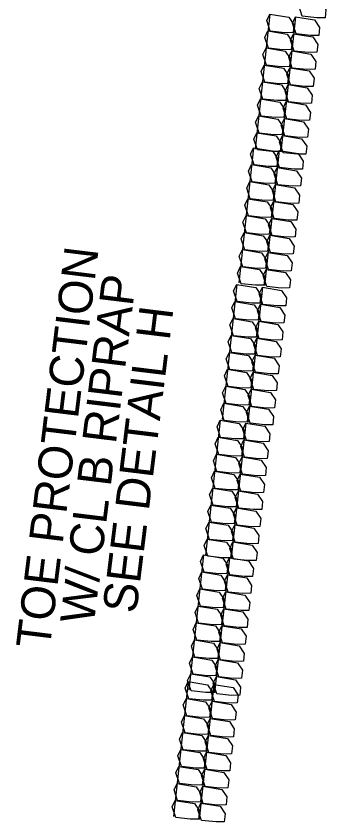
# Model space of a CAD drawing. Extents: x 465700 to 483515, y 488970 to 507540.
# Drawn here: x 481164.1 to 481209.7, y 490401.6 to 490519.9 of the extents above; entities that cross this region are included whole.
import ezdxf

# ---------------------------------------------------------------- set-up
doc = ezdxf.new("R2010")
doc.units = 0
doc.layers.add('Prop Erosion Embankment Toe Protection CELL', color=7, linetype='Continuous')
doc.layers.add('Prop Erosion Embankment Toe Protection Label', color=7, linetype='Continuous')

msp = doc.modelspace()

# ---------------------------------------------------------------- linework, layer by layer
at = {"layer": 'Prop Erosion Embankment Toe Protection CELL'}
for p, q in [((481201.41, 490520.24), (481199.25, 490500.36)), ((481205.19, 490519.83), (481203.03, 490499.95)), ((481199.01, 490500.55), (481196.84, 490480.67)), ((481202.79, 490500.14), (481200.62, 490480.26)), ((481196.55, 490480.41), (481194.38, 490460.53)), ((481200.33, 490480), (481198.16, 490460.12)), ((481194.11, 490460.42), (481191.94, 490440.54)), ((481197.88, 490460.01), (481195.72, 490440.13)), ((481191.68, 490440.59), (481189.52, 490420.7)), ((481195.46, 490440.18), (481193.3, 490420.29)), ((481189.41, 490421.95), (481187.24, 490402.07)), ((481193.19, 490421.54), (481191.02, 490401.66))]:
    msp.add_line(p, q, dxfattribs=at)
for points in [[(481209.54, 490519.69), (481208.33, 490519.67), (481206.19, 490519.91), (481205.66, 490521.47), (481206.11, 490522.43), (481208.93, 490521.97), (481209.67, 490520.88), (481209.54, 490519.69)], [(481204.84, 490517.5), (481203.63, 490517.48), (481201.49, 490517.72), (481200.96, 490519.28), (481201.41, 490520.24), (481204.23, 490519.78), (481204.96, 490518.67), (481204.84, 490517.5)], [(481208.61, 490517.09), (481207.41, 490517.07), (481205.27, 490517.3), (481204.73, 490518.87), (481205.19, 490519.83), (481208.01, 490519.37), (481208.74, 490518.26), (481208.61, 490517.09)], [(481204.57, 490515.02), (481203.35, 490514.97), (481201.22, 490515.21), (481200.69, 490516.8), (481201.14, 490517.75), (481203.96, 490517.27), (481204.69, 490516.16), (481204.57, 490515.02)], [(481208.34, 490514.61), (481207.13, 490514.56), (481204.99, 490514.79), (481204.46, 490516.39), (481204.92, 490517.34), (481207.73, 490516.86), (481208.47, 490515.75), (481208.34, 490514.61)], [(481204.29, 490512.51), (481203.08, 490512.46), (481200.94, 490512.7), (481200.41, 490514.29), (481200.87, 490515.24), (481203.68, 490514.76), (481204.42, 490513.67), (481204.29, 490512.51)], [(481208.07, 490512.1), (481206.86, 490512.05), (481204.72, 490512.28), (481204.19, 490513.88), (481204.65, 490514.83), (481207.46, 490514.35), (481208.2, 490513.26), (481208.07, 490512.1)], [(481204.02, 490510), (481202.81, 490509.98), (481200.67, 490510.21), (481200.14, 490511.78), (481200.6, 490512.73), (481203.41, 490512.28), (481204.15, 490511.19), (481204.02, 490510)], [(481207.8, 490509.59), (481206.59, 490509.57), (481204.45, 490509.8), (481203.92, 490511.37), (481204.37, 490512.32), (481207.19, 490511.86), (481207.93, 490510.78), (481207.8, 490509.59)], [(481203.75, 490507.51), (481202.54, 490507.49), (481200.4, 490507.72), (481199.87, 490509.29), (481200.33, 490510.25), (481203.14, 490509.79), (481203.88, 490508.68), (481203.75, 490507.51)], [(481207.53, 490507.1), (481206.32, 490507.08), (481204.18, 490507.31), (481203.65, 490508.88), (481204.1, 490509.84), (481206.92, 490509.38), (481207.65, 490508.27), (481207.53, 490507.1)], [(481203.48, 490505.03), (481202.27, 490504.98), (481200.13, 490505.21), (481199.6, 490506.81), (481200.05, 490507.76), (481202.87, 490507.28), (481203.6, 490506.17), (481203.48, 490505.03)], [(481207.26, 490504.61), (481206.04, 490504.57), (481203.91, 490504.8), (481203.38, 490506.4), (481203.83, 490507.35), (481206.65, 490506.87), (481207.38, 490505.76), (481207.26, 490504.61)], [(481203.21, 490502.52), (481201.99, 490502.47), (481199.86, 490502.7), (481199.33, 490504.3), (481199.78, 490505.25), (481202.6, 490504.77), (481203.33, 490503.68), (481203.21, 490502.52)], [(481206.98, 490502.1), (481205.77, 490502.06), (481203.63, 490502.29), (481203.1, 490503.88), (481203.56, 490504.84), (481206.37, 490504.36), (481207.11, 490503.27), (481206.98, 490502.1)], [(481202.93, 490500.01), (481201.72, 490499.99), (481199.59, 490500.22), (481199.05, 490501.79), (481199.51, 490502.74), (481202.33, 490502.28), (481203.06, 490501.2), (481202.93, 490500.01)], [(481206.71, 490499.59), (481205.5, 490499.58), (481203.36, 490499.81), (481202.83, 490501.37), (481203.29, 490502.33), (481206.1, 490501.87), (481206.84, 490500.79), (481206.71, 490499.59)], [(481202.43, 490497.81), (481201.22, 490497.8), (481199.09, 490498.03), (481198.55, 490499.59), (481199.01, 490500.55), (481201.83, 490500.09), (481202.56, 490498.98), (481202.43, 490497.81)], [(481206.21, 490497.4), (481205, 490497.38), (481202.86, 490497.62), (481202.33, 490499.18), (481202.79, 490500.14), (481205.6, 490499.68), (481206.34, 490498.57), (481206.21, 490497.4)], [(481202.16, 490495.33), (481200.95, 490495.29), (481198.81, 490495.52), (481198.28, 490497.11), (481198.74, 490498.07), (481201.55, 490497.58), (481202.29, 490496.47), (481202.16, 490495.33)], [(481205.94, 490494.92), (481204.73, 490494.87), (481202.59, 490495.11), (481202.06, 490496.7), (481202.52, 490497.65), (481205.33, 490497.17), (481206.06, 490496.06), (481205.94, 490494.92)], [(481201.89, 490492.82), (481200.68, 490492.77), (481198.54, 490493.01), (481198.01, 490494.6), (481198.46, 490495.56), (481201.28, 490495.07), (481202.02, 490493.99), (481201.89, 490492.82)], [(481205.67, 490492.41), (481204.45, 490492.36), (481202.32, 490492.6), (481201.79, 490494.19), (481202.24, 490495.14), (481205.06, 490494.66), (481205.79, 490493.58), (481205.67, 490492.41)], [(481201.62, 490490.31), (481200.41, 490490.29), (481198.27, 490490.52), (481197.74, 490492.09), (481198.19, 490493.05), (481201.01, 490492.59), (481201.75, 490491.5), (481201.62, 490490.31)], [(481205.39, 490489.9), (481204.18, 490489.88), (481202.05, 490490.11), (481201.51, 490491.68), (481201.97, 490492.63), (481204.79, 490492.18), (481205.52, 490491.09), (481205.39, 490489.9)], [(481201.34, 490487.82), (481200.14, 490487.8), (481198, 490488.04), (481197.46, 490489.6), (481197.92, 490490.56), (481200.74, 490490.1), (481201.47, 490488.99), (481201.34, 490487.82)], [(481205.12, 490487.41), (481203.91, 490487.39), (481201.78, 490487.63), (481201.24, 490489.19), (481201.7, 490490.15), (481204.52, 490489.69), (481205.25, 490488.58), (481205.12, 490487.41)], [(481201.07, 490485.34), (481199.86, 490485.29), (481197.72, 490485.53), (481197.19, 490487.12), (481197.65, 490488.07), (481200.46, 490487.59), (481201.2, 490486.48), (481201.07, 490485.34)], [(481204.85, 490484.93), (481203.64, 490484.88), (481201.5, 490485.12), (481200.97, 490486.71), (481201.43, 490487.66), (481204.24, 490487.18), (481204.98, 490486.07), (481204.85, 490484.93)], [(481200.8, 490482.83), (481199.59, 490482.78), (481197.45, 490483.02), (481196.92, 490484.61), (481197.38, 490485.56), (481200.19, 490485.08), (481200.93, 490484), (481200.8, 490482.83)], [(481204.58, 490482.42), (481203.37, 490482.37), (481201.23, 490482.61), (481200.7, 490484.2), (481201.15, 490485.15), (481203.97, 490484.67), (481204.71, 490483.59), (481204.58, 490482.42)], [(481200.53, 490480.32), (481199.32, 490480.3), (481197.18, 490480.53), (481196.65, 490482.1), (481197.1, 490483.05), (481199.92, 490482.6), (481200.66, 490481.51), (481200.53, 490480.32)], [(481204.31, 490479.91), (481203.1, 490479.89), (481200.96, 490480.12), (481200.43, 490481.69), (481200.88, 490482.64), (481203.7, 490482.19), (481204.44, 490481.1), (481204.31, 490479.91)], [(481199.97, 490477.68), (481198.76, 490477.66), (481196.63, 490477.89), (481196.09, 490479.46), (481196.55, 490480.41), (481199.37, 490479.96), (481200.1, 490478.84), (481199.97, 490477.68)], [(481203.75, 490477.26), (481202.54, 490477.25), (481200.4, 490477.48), (481199.87, 490479.05), (481200.33, 490480), (481203.14, 490479.54), (481203.88, 490478.43), (481203.75, 490477.26)], [(481199.7, 490475.19), (481198.49, 490475.15), (481196.35, 490475.38), (481195.82, 490476.97), (481196.28, 490477.93), (481199.09, 490477.44), (481199.83, 490476.33), (481199.7, 490475.19)], [(481203.48, 490474.78), (481202.27, 490474.74), (481200.13, 490474.97), (481199.6, 490476.56), (481200.06, 490477.52), (481202.87, 490477.03), (481203.6, 490475.92), (481203.48, 490474.78)], [(481199.43, 490472.68), (481198.22, 490472.64), (481196.08, 490472.87), (481195.55, 490474.46), (481196, 490475.42), (481198.82, 490474.93), (481199.56, 490473.85), (481199.43, 490472.68)], [(481203.21, 490472.27), (481201.99, 490472.23), (481199.86, 490472.46), (481199.33, 490474.05), (481199.78, 490475.01), (481202.6, 490474.52), (481203.33, 490473.44), (481203.21, 490472.27)], [(481199.16, 490470.17), (481197.95, 490470.15), (481195.81, 490470.38), (481195.28, 490471.95), (481195.73, 490472.91), (481198.55, 490472.45), (481199.29, 490471.36), (481199.16, 490470.17)], [(481202.93, 490469.76), (481201.72, 490469.74), (481199.59, 490469.97), (481199.05, 490471.54), (481199.51, 490472.5), (481202.33, 490472.04), (481203.06, 490470.95), (481202.93, 490469.76)], [(481198.88, 490467.69), (481197.68, 490467.67), (481195.54, 490467.9), (481195, 490469.47), (481195.46, 490470.42), (481198.28, 490469.96), (481199.01, 490468.85), (481198.88, 490467.69)], [(481202.66, 490467.27), (481201.45, 490467.25), (481199.32, 490467.49), (481198.78, 490469.05), (481199.24, 490470.01), (481202.06, 490469.55), (481202.79, 490468.44), (481202.66, 490467.27)], [(481198.61, 490465.2), (481197.4, 490465.16), (481195.27, 490465.39), (481194.73, 490466.98), (481195.19, 490467.94), (481198, 490467.45), (481198.74, 490466.34), (481198.61, 490465.2)], [(481202.39, 490464.79), (481201.18, 490464.74), (481199.04, 490464.98), (481198.51, 490466.57), (481198.97, 490467.53), (481201.78, 490467.04), (481202.52, 490465.93), (481202.39, 490464.79)], [(481198.34, 490462.69), (481197.13, 490462.65), (481194.99, 490462.88), (481194.46, 490464.47), (481194.92, 490465.43), (481197.73, 490464.94), (481198.47, 490463.86), (481198.34, 490462.69)], [(481202.12, 490462.28), (481200.91, 490462.23), (481198.77, 490462.47), (481198.24, 490464.06), (481198.69, 490465.01), (481201.51, 490464.53), (481202.25, 490463.45), (481202.12, 490462.28)], [(481198.07, 490460.18), (481196.86, 490460.16), (481194.72, 490460.39), (481194.19, 490461.96), (481194.64, 490462.92), (481197.46, 490462.46), (481198.2, 490461.37), (481198.07, 490460.18)], [(481201.85, 490459.77), (481200.64, 490459.75), (481198.5, 490459.98), (481197.97, 490461.55), (481198.42, 490462.5), (481201.24, 490462.05), (481201.98, 490460.96), (481201.85, 490459.77)], [(481197.53, 490457.69), (481196.32, 490457.67), (481194.18, 490457.9), (481193.65, 490459.47), (481194.11, 490460.42), (481196.92, 490459.97), (481197.66, 490458.86), (481197.53, 490457.69)], [(481201.31, 490457.28), (481200.1, 490457.26), (481197.96, 490457.49), (481197.43, 490459.06), (481197.88, 490460.01), (481200.7, 490459.56), (481201.44, 490458.44), (481201.31, 490457.28)], [(481197.26, 490455.2), (481196.05, 490455.16), (481193.91, 490455.39), (481193.38, 490456.98), (481193.84, 490457.94), (481196.65, 490457.46), (481197.39, 490456.35), (481197.26, 490455.2)], [(481201.04, 490454.79), (481199.83, 490454.75), (481197.69, 490454.98), (481197.16, 490456.57), (481197.61, 490457.53), (481200.43, 490457.05), (481201.16, 490455.93), (481201.04, 490454.79)], [(481196.99, 490452.69), (481195.78, 490452.65), (481193.64, 490452.88), (481193.11, 490454.47), (481193.56, 490455.43), (481196.38, 490454.95), (481197.11, 490453.86), (481196.99, 490452.69)], [(481200.77, 490452.28), (481199.55, 490452.24), (481197.42, 490452.47), (481196.88, 490454.06), (481197.34, 490455.02), (481200.16, 490454.54), (481200.89, 490453.45), (481200.77, 490452.28)], [(481196.71, 490450.18), (481195.51, 490450.16), (481193.37, 490450.4), (481192.83, 490451.96), (481193.29, 490452.92), (481196.11, 490452.46), (481196.84, 490451.38), (481196.71, 490450.18)], [(481200.49, 490449.77), (481199.28, 490449.75), (481197.15, 490449.98), (481196.61, 490451.55), (481197.07, 490452.51), (481199.88, 490452.05), (481200.62, 490450.96), (481200.49, 490449.77)], [(481196.44, 490447.7), (481195.23, 490447.68), (481193.1, 490447.91), (481192.56, 490449.48), (481193.02, 490450.43), (481195.84, 490449.98), (481196.57, 490448.86), (481196.44, 490447.7)], [(481200.22, 490447.29), (481199.01, 490447.27), (481196.87, 490447.5), (481196.34, 490449.07), (481196.8, 490450.02), (481199.61, 490449.56), (481200.35, 490448.45), (481200.22, 490447.29)], [(481196.17, 490445.21), (481194.96, 490445.17), (481192.82, 490445.4), (481192.29, 490446.99), (481192.75, 490447.95), (481195.56, 490447.47), (481196.3, 490446.35), (481196.17, 490445.21)], [(481199.95, 490444.8), (481198.74, 490444.76), (481196.6, 490444.99), (481196.07, 490446.58), (481196.53, 490447.54), (481199.34, 490447.05), (481200.08, 490445.94), (481199.95, 490444.8)], [(481195.9, 490442.7), (481194.69, 490442.66), (481192.55, 490442.89), (481192.02, 490444.48), (481192.48, 490445.44), (481195.29, 490444.96), (481196.03, 490443.87), (481195.9, 490442.7)], [(481199.68, 490442.29), (481198.47, 490442.25), (481196.33, 490442.48), (481195.8, 490444.07), (481196.25, 490445.03), (481199.07, 490444.54), (481199.8, 490443.46), (481199.68, 490442.29)], [(481195.63, 490440.19), (481194.42, 490440.17), (481192.28, 490440.4), (481191.75, 490441.97), (481192.2, 490442.93), (481195.02, 490442.47), (481195.76, 490441.38), (481195.63, 490440.19)], [(481199.4, 490439.78), (481198.2, 490439.76), (481196.06, 490439.99), (481195.52, 490441.56), (481195.98, 490442.52), (481198.8, 490442.06), (481199.53, 490440.97), (481199.4, 490439.78)], [(481195.11, 490437.85), (481193.9, 490437.83), (481191.76, 490438.06), (481191.23, 490439.63), (481191.68, 490440.59), (481194.5, 490440.13), (481195.24, 490439.02), (481195.11, 490437.85)], [(481198.89, 490437.44), (481197.68, 490437.42), (481195.54, 490437.65), (481195.01, 490439.22), (481195.46, 490440.18), (481198.28, 490439.72), (481199.01, 490438.61), (481198.89, 490437.44)], [(481194.84, 490435.36), (481193.63, 490435.32), (481191.49, 490435.55), (481190.96, 490437.14), (481191.41, 490438.1), (481194.23, 490437.62), (481194.96, 490436.51), (481194.84, 490435.36)], [(481198.62, 490434.95), (481197.4, 490434.91), (481195.27, 490435.14), (481194.74, 490436.73), (481195.19, 490437.69), (481198.01, 490437.21), (481198.74, 490436.1), (481198.62, 490434.95)], [(481194.56, 490432.85), (481193.35, 490432.81), (481191.22, 490433.04), (481190.68, 490434.63), (481191.14, 490435.59), (481193.95, 490435.11), (481194.69, 490434.02), (481194.56, 490432.85)], [(481198.34, 490432.44), (481197.13, 490432.4), (481194.99, 490432.63), (481194.46, 490434.22), (481194.92, 490435.18), (481197.73, 490434.7), (481198.47, 490433.61), (481198.34, 490432.44)], [(481194.29, 490430.34), (481193.08, 490430.33), (481190.94, 490430.56), (481190.41, 490432.12), (481190.87, 490433.08), (481193.68, 490432.62), (481194.42, 490431.54), (481194.29, 490430.34)], [(481198.07, 490429.93), (481196.86, 490429.91), (481194.72, 490430.15), (481194.19, 490431.71), (481194.64, 490432.67), (481197.46, 490432.21), (481198.2, 490431.13), (481198.07, 490429.93)], [(481194.02, 490427.86), (481192.81, 490427.84), (481190.67, 490428.07), (481190.14, 490429.64), (481190.6, 490430.6), (481193.41, 490430.14), (481194.15, 490429.03), (481194.02, 490427.86)], [(481197.8, 490427.45), (481196.59, 490427.43), (481194.45, 490427.66), (481193.92, 490429.23), (481194.37, 490430.18), (481197.19, 490429.73), (481197.93, 490428.62), (481197.8, 490427.45)], [(481193.75, 490425.37), (481192.54, 490425.33), (481190.4, 490425.56), (481189.87, 490427.15), (481190.33, 490428.11), (481193.14, 490427.63), (481193.87, 490426.52), (481193.75, 490425.37)], [(481197.53, 490424.96), (481196.32, 490424.92), (481194.18, 490425.15), (481193.65, 490426.74), (481194.1, 490427.7), (481196.92, 490427.22), (481197.65, 490426.11), (481197.53, 490424.96)], [(481193.48, 490422.86), (481192.27, 490422.82), (481190.13, 490423.05), (481189.6, 490424.64), (481190.05, 490425.6), (481192.87, 490425.12), (481193.6, 490424.03), (481193.48, 490422.86)], [(481197.25, 490422.45), (481196.04, 490422.41), (481193.91, 490422.64), (481193.37, 490424.23), (481193.83, 490425.19), (481196.64, 490424.71), (481197.38, 490423.62), (481197.25, 490422.45)], [(481193.2, 490420.35), (481191.99, 490420.33), (481189.86, 490420.57), (481189.32, 490422.13), (481189.78, 490423.09), (481192.6, 490422.63), (481193.33, 490421.55), (481193.2, 490420.35)], [(481196.98, 490419.94), (481195.77, 490419.92), (481193.63, 490420.16), (481193.1, 490421.72), (481193.56, 490422.68), (481196.37, 490422.22), (481197.11, 490421.14), (481196.98, 490419.94)], [(481192.83, 490419.21), (481191.62, 490419.2), (481189.49, 490419.43), (481188.95, 490420.99), (481189.41, 490421.95), (481192.23, 490421.49), (481192.96, 490420.38), (481192.83, 490419.21)], [(481196.61, 490418.8), (481195.4, 490418.78), (481193.26, 490419.02), (481192.73, 490420.58), (481193.19, 490421.54), (481196, 490421.08), (481196.74, 490419.97), (481196.61, 490418.8)], [(481192.56, 490416.73), (481191.35, 490416.68), (481189.21, 490416.92), (481188.68, 490418.51), (481189.14, 490419.47), (481191.95, 490418.98), (481192.69, 490417.87), (481192.56, 490416.73)], [(481196.34, 490416.32), (481195.13, 490416.27), (481192.99, 490416.51), (481192.46, 490418.1), (481192.92, 490419.05), (481195.73, 490418.57), (481196.46, 490417.46), (481196.34, 490416.32)], [(481192.29, 490414.22), (481191.08, 490414.17), (481188.94, 490414.41), (481188.41, 490416), (481188.86, 490416.96), (481191.68, 490416.47), (481192.42, 490415.39), (481192.29, 490414.22)], [(481196.07, 490413.81), (481194.85, 490413.76), (481192.72, 490414), (481192.19, 490415.59), (481192.64, 490416.54), (481195.46, 490416.06), (481196.19, 490414.98), (481196.07, 490413.81)], [(481192.02, 490411.71), (481190.81, 490411.69), (481188.67, 490411.92), (481188.13, 490413.49), (481188.59, 490414.45), (481191.41, 490413.99), (481192.14, 490412.9), (481192.02, 490411.71)], [(481195.79, 490411.3), (481194.58, 490411.28), (481192.45, 490411.51), (481191.91, 490413.08), (481192.37, 490414.03), (481195.19, 490413.58), (481195.92, 490412.49), (481195.79, 490411.3)], [(481191.74, 490409.22), (481190.54, 490409.2), (481188.4, 490409.44), (481187.86, 490411), (481188.32, 490411.96), (481191.14, 490411.5), (481191.87, 490410.39), (481191.74, 490409.22)], [(481195.52, 490408.81), (481194.31, 490408.79), (481192.18, 490409.03), (481191.64, 490410.59), (481192.1, 490411.55), (481194.92, 490411.09), (481195.65, 490409.98), (481195.52, 490408.81)], [(481191.47, 490406.74), (481190.26, 490406.69), (481188.12, 490406.93), (481187.59, 490408.52), (481188.05, 490409.47), (481190.86, 490408.99), (481191.6, 490407.88), (481191.47, 490406.74)], [(481195.25, 490406.33), (481194.04, 490406.28), (481191.9, 490406.52), (481191.37, 490408.11), (481191.83, 490409.06), (481194.64, 490408.58), (481195.38, 490407.47), (481195.25, 490406.33)], [(481191.2, 490404.23), (481189.99, 490404.18), (481187.85, 490404.42), (481187.32, 490406.01), (481187.78, 490406.96), (481190.59, 490406.48), (481191.33, 490405.4), (481191.2, 490404.23)], [(481194.98, 490403.82), (481193.77, 490403.77), (481191.63, 490404.01), (481191.1, 490405.6), (481191.55, 490406.55), (481194.37, 490406.07), (481195.11, 490404.98), (481194.98, 490403.82)], [(481190.93, 490401.72), (481189.72, 490401.7), (481187.58, 490401.93), (481187.05, 490403.5), (481187.5, 490404.45), (481190.32, 490404), (481191.06, 490402.91), (481190.93, 490401.72)], [(481194.71, 490401.31), (481193.5, 490401.29), (481191.36, 490401.52), (481190.83, 490403.09), (481191.28, 490404.04), (481194.1, 490403.59), (481194.84, 490402.5), (481194.71, 490401.31)]]:
    msp.add_lwpolyline(points, dxfattribs=at)

# ---------------------------------------------------------------- texts
at = {"layer": 'Prop Erosion Embankment Toe Protection Label'}
for s, p in [('TOE PROTECTION', (481169.03, 490426.63)), ('W/ CL B RIPRAP', (481175.52, 490430.28)), ('SEE DETAIL H', (481181.76, 490431.87))]:
    msp.add_text(s, height=5, rotation=83.0365, dxfattribs=at).set_placement(p)

doc.saveas('drawing.dxf')
